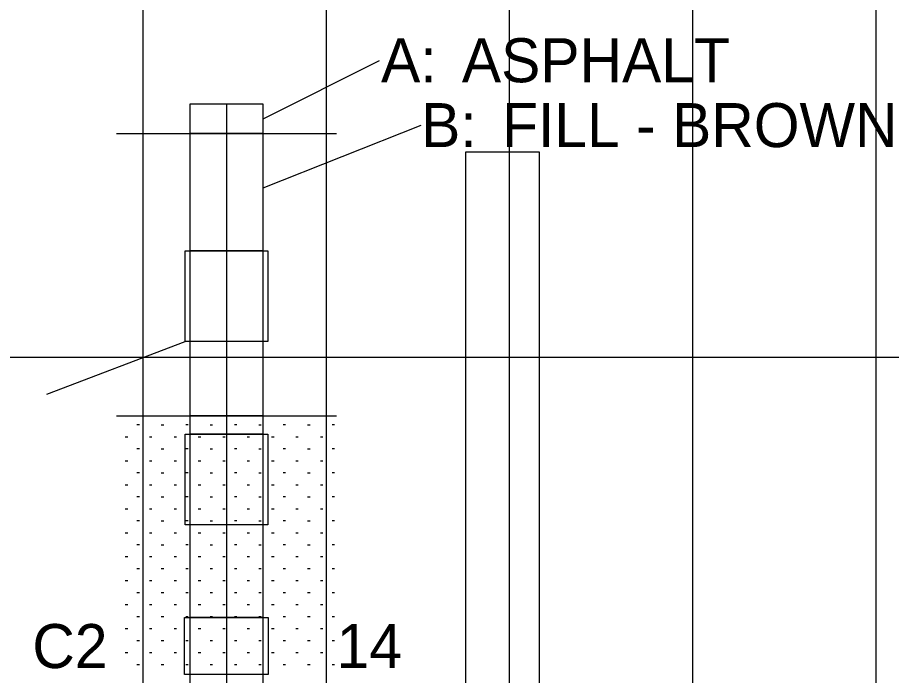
# Model space of a CAD drawing. Extents: x -290 to 297, y 616 to 861.
# Drawn here: x 3.15 to 50.83, y 712.65 to 748.52 of the extents above; entities that cross this region are included whole.
import ezdxf

# ---------------------------------------------------------------- set-up
doc = ezdxf.new("R2010")
doc.units = 0
for name, color, linetype in [('Default', 7, 'Continuous'), ('DisROW Proposed Temp Easements', 7, 'Continuous'), ('Draft_4', 7, 'Continuous'), ('MeshTop', 7, 'Continuous'), ('SewerSanitary', 7, 'Continuous'), ('SewerStormPipe', 7, 'Continuous'), ('TextAlignment', 7, 'Continuous'), ('TextAlignmentSml', 7, 'Continuous'), ('Utility-Water - alignment', 7, 'Continuous'), ('V-SWLK-CONC', 7, 'Continuous')]:
    doc.layers.add(name, color=color, linetype=linetype)

msp = doc.modelspace()

# ---------------------------------------------------------------- linework, layer by layer
at = {"layer": 'Default'}
for p, q in [((14.546, 743.8), (14.546, 682.8)), ((16.546, 742.2), (12.546, 742.2)), ((16.546, 726.8), (12.546, 726.8))]:
    msp.add_line(p, q, dxfattribs=at)
at = {"layer": 'DisROW Proposed Temp Easements'}
for points in [[(12.291, 735.8), (16.801, 735.8), (16.801, 730.863), (12.291, 730.863)], [(12.291, 725.8), (16.801, 725.8), (16.801, 720.863), (12.291, 720.863)], [(12.258, 715.8), (16.834, 715.8), (16.834, 712.704), (12.258, 712.704)]]:
    msp.add_lwpolyline(points, close=True, dxfattribs=at)
at = {"layer": 'Draft_4'}
msp.add_lwpolyline([(16.546, 726.8), (12.546, 726.8), (12.546, 705.8), (16.546, 705.8)], close=True, dxfattribs=at)
at = {"layer": 'MeshTop'}
msp.add_lwpolyline([(16.546, 743.8), (12.546, 743.8), (12.546, 742.2), (16.546, 742.2)], close=True, dxfattribs=at)
at = {"layer": 'SewerSanitary'}
for p, q in [((16.546, 735.8), (12.546, 735.8)), ((16.546, 725.8), (12.546, 725.8))]:
    msp.add_line(p, q, dxfattribs=at)
at = {"layer": 'SewerStormPipe'}
msp.add_line((16.546, 715.8), (12.546, 715.8), dxfattribs=at)
at = {"layer": 'TextAlignment'}
for p, q in [((20, 630), (20, 787.989)), ((40, 630), (40, 787.989)), ((-275.612, 730), (284.208, 730))]:
    msp.add_line(p, q, dxfattribs=at)
at = {"layer": 'TextAlignmentSml'}
for p, q in [((10, 630), (10, 787.989)), ((30, 630), (30, 787.989)), ((50, 630), (50, 787.989))]:
    msp.add_line(p, q, dxfattribs=at)
at = {"layer": 'Utility-Water - alignment'}
msp.add_lwpolyline([(16.546, 742.2), (12.546, 742.2), (12.546, 726.8), (16.546, 726.8)], close=True, dxfattribs=at)
at = {"layer": 'V-SWLK-CONC'}
for p, q in [((16.546, 743), (22.898, 746.185)), ((16.546, 739.24), (25.17, 742.655)), ((8.546, 742.2), (20.546, 742.2)), ((4.756, 727.978), (12.291, 730.863)), ((8.546, 726.8), (20.546, 726.8)), ((9.667, 726.33), (9.799, 726.33)), ((10.996, 726.317), (11.128, 726.317)), ((12.327, 726.33), (12.459, 726.33)), ((13.657, 726.317), (13.789, 726.317)), ((14.988, 726.33), (15.12, 726.33)), ((16.317, 726.317), (16.449, 726.317)), ((17.649, 726.33), (17.781, 726.33)), ((18.978, 726.317), (19.11, 726.317)), ((20.31, 726.33), (20.442, 726.33)), ((9.032, 725.663), (9.164, 725.663)), ((10.352, 725.663), (10.484, 725.663)), ((11.693, 725.663), (11.825, 725.663)), ((13.013, 725.663), (13.145, 725.663)), ((14.354, 725.663), (14.486, 725.663)), ((15.674, 725.663), (15.806, 725.663)), ((17.015, 725.663), (17.147, 725.663)), ((18.335, 725.663), (18.467, 725.663)), ((19.675, 725.663), (19.807, 725.663)), ((9.667, 725.023), (9.799, 725.023)), ((10.996, 725.01), (11.128, 725.01)), ((12.327, 725.023), (12.459, 725.023)), ((13.657, 725.01), (13.789, 725.01)), ((14.988, 725.023), (15.12, 725.023)), ((16.317, 725.01), (16.449, 725.01)), ((17.649, 725.023), (17.781, 725.023)), ((18.978, 725.01), (19.11, 725.01)), ((20.31, 725.023), (20.442, 725.023)), ((9.032, 724.356), (9.164, 724.356)), ((10.352, 724.356), (10.484, 724.356)), ((11.693, 724.356), (11.825, 724.356)), ((13.013, 724.356), (13.145, 724.356)), ((14.354, 724.356), (14.486, 724.356)), ((15.674, 724.356), (15.806, 724.356)), ((17.015, 724.356), (17.147, 724.356)), ((18.335, 724.356), (18.467, 724.356)), ((19.675, 724.356), (19.807, 724.356)), ((9.667, 723.715), (9.799, 723.715)), ((10.996, 723.702), (11.128, 723.702)), ((12.327, 723.715), (12.459, 723.715)), ((13.657, 723.702), (13.789, 723.702)), ((14.988, 723.715), (15.12, 723.715)), ((16.317, 723.702), (16.449, 723.702)), ((17.649, 723.715), (17.781, 723.715)), ((18.978, 723.702), (19.11, 723.702)), ((20.31, 723.715), (20.442, 723.715)), ((9.032, 723.048), (9.164, 723.048)), ((10.352, 723.048), (10.484, 723.048)), ((11.693, 723.048), (11.825, 723.048)), ((13.013, 723.048), (13.145, 723.048)), ((14.354, 723.048), (14.486, 723.048)), ((15.674, 723.048), (15.806, 723.048)), ((17.015, 723.048), (17.147, 723.048)), ((18.335, 723.048), (18.467, 723.048)), ((19.675, 723.048), (19.807, 723.048)), ((9.667, 722.408), (9.799, 722.408)), ((10.996, 722.395), (11.128, 722.395)), ((12.327, 722.408), (12.459, 722.408)), ((13.657, 722.395), (13.789, 722.395)), ((14.988, 722.408), (15.12, 722.408)), ((16.317, 722.395), (16.449, 722.395)), ((17.649, 722.408), (17.781, 722.408)), ((18.978, 722.395), (19.11, 722.395)), ((20.31, 722.408), (20.442, 722.408)), ((9.032, 721.741), (9.164, 721.741)), ((10.352, 721.741), (10.484, 721.741)), ((11.693, 721.741), (11.825, 721.741)), ((13.013, 721.741), (13.145, 721.741)), ((14.354, 721.741), (14.486, 721.741)), ((15.674, 721.741), (15.806, 721.741)), ((17.015, 721.741), (17.147, 721.741)), ((18.335, 721.741), (18.467, 721.741)), ((19.675, 721.741), (19.807, 721.741)), ((9.667, 721.1), (9.799, 721.1)), ((10.996, 721.087), (11.128, 721.087)), ((12.327, 721.1), (12.459, 721.1)), ((13.657, 721.087), (13.789, 721.087)), ((14.988, 721.1), (15.12, 721.1)), ((16.317, 721.087), (16.449, 721.087)), ((17.649, 721.1), (17.781, 721.1)), ((18.978, 721.087), (19.11, 721.087)), ((20.31, 721.1), (20.442, 721.1)), ((9.032, 720.433), (9.164, 720.433)), ((10.352, 720.433), (10.484, 720.433)), ((11.693, 720.433), (11.825, 720.433)), ((13.013, 720.433), (13.145, 720.433)), ((14.354, 720.433), (14.486, 720.433)), ((15.674, 720.433), (15.806, 720.433)), ((17.015, 720.433), (17.147, 720.433)), ((18.335, 720.433), (18.467, 720.433)), ((19.675, 720.433), (19.807, 720.433)), ((9.667, 719.793), (9.799, 719.793)), ((10.996, 719.779), (11.128, 719.779)), ((12.327, 719.793), (12.459, 719.793)), ((13.657, 719.779), (13.789, 719.779)), ((14.988, 719.793), (15.12, 719.793)), ((16.317, 719.779), (16.449, 719.779)), ((17.649, 719.793), (17.781, 719.793)), ((18.978, 719.779), (19.11, 719.779)), ((20.31, 719.793), (20.442, 719.793)), ((9.032, 719.126), (9.164, 719.126)), ((10.352, 719.126), (10.484, 719.126)), ((11.693, 719.126), (11.825, 719.126)), ((13.013, 719.126), (13.145, 719.126)), ((14.354, 719.126), (14.486, 719.126)), ((15.674, 719.126), (15.806, 719.126)), ((17.015, 719.126), (17.147, 719.126)), ((18.335, 719.126), (18.467, 719.126)), ((19.675, 719.126), (19.807, 719.126)), ((9.667, 718.485), (9.799, 718.485)), ((10.996, 718.472), (11.128, 718.472)), ((12.327, 718.485), (12.459, 718.485)), ((13.657, 718.472), (13.789, 718.472)), ((14.988, 718.485), (15.12, 718.485)), ((16.317, 718.472), (16.449, 718.472)), ((17.649, 718.485), (17.781, 718.485)), ((18.978, 718.472), (19.11, 718.472)), ((20.31, 718.485), (20.442, 718.485)), ((9.032, 717.818), (9.164, 717.818)), ((10.352, 717.818), (10.484, 717.818)), ((11.693, 717.818), (11.825, 717.818)), ((13.013, 717.818), (13.145, 717.818)), ((14.354, 717.818), (14.486, 717.818)), ((15.674, 717.818), (15.806, 717.818)), ((17.015, 717.818), (17.147, 717.818)), ((18.335, 717.818), (18.467, 717.818)), ((19.675, 717.818), (19.807, 717.818)), ((9.667, 717.178), (9.799, 717.178)), ((10.996, 717.164), (11.128, 717.164)), ((12.327, 717.178), (12.459, 717.178)), ((13.657, 717.164), (13.789, 717.164)), ((14.988, 717.178), (15.12, 717.178)), ((16.317, 717.164), (16.449, 717.164)), ((17.649, 717.178), (17.781, 717.178)), ((18.978, 717.164), (19.11, 717.164)), ((20.31, 717.178), (20.442, 717.178)), ((9.032, 716.511), (9.164, 716.511)), ((10.352, 716.511), (10.484, 716.511)), ((11.693, 716.511), (11.825, 716.511)), ((13.013, 716.511), (13.145, 716.511)), ((14.354, 716.511), (14.486, 716.511)), ((15.674, 716.511), (15.806, 716.511)), ((17.015, 716.511), (17.147, 716.511)), ((18.335, 716.511), (18.467, 716.511)), ((19.675, 716.511), (19.807, 716.511)), ((9.667, 715.87), (9.799, 715.87)), ((10.996, 715.857), (11.128, 715.857)), ((12.327, 715.87), (12.459, 715.87)), ((13.657, 715.857), (13.789, 715.857)), ((14.988, 715.87), (15.12, 715.87)), ((16.317, 715.857), (16.449, 715.857)), ((17.649, 715.87), (17.781, 715.87)), ((18.978, 715.857), (19.11, 715.857)), ((20.31, 715.87), (20.442, 715.87)), ((9.032, 715.203), (9.164, 715.203)), ((10.352, 715.203), (10.484, 715.203)), ((11.693, 715.203), (11.825, 715.203)), ((13.013, 715.203), (13.145, 715.203)), ((14.354, 715.203), (14.486, 715.203)), ((15.674, 715.203), (15.806, 715.203)), ((17.015, 715.203), (17.147, 715.203)), ((18.335, 715.203), (18.467, 715.203)), ((19.675, 715.203), (19.807, 715.203)), ((9.667, 714.563), (9.799, 714.563)), ((10.996, 714.549), (11.128, 714.549)), ((12.327, 714.563), (12.459, 714.563)), ((13.657, 714.549), (13.789, 714.549)), ((14.988, 714.563), (15.12, 714.563)), ((16.317, 714.549), (16.449, 714.549)), ((17.649, 714.563), (17.781, 714.563)), ((18.978, 714.549), (19.11, 714.549)), ((20.31, 714.563), (20.442, 714.563)), ((9.032, 713.896), (9.164, 713.896)), ((10.352, 713.896), (10.484, 713.896)), ((11.693, 713.896), (11.825, 713.896)), ((13.013, 713.896), (13.145, 713.896)), ((14.354, 713.896), (14.486, 713.896)), ((15.674, 713.896), (15.806, 713.896)), ((17.015, 713.896), (17.147, 713.896)), ((18.335, 713.896), (18.467, 713.896)), ((19.675, 713.896), (19.807, 713.896)), ((9.667, 713.255), (9.799, 713.255)), ((10.996, 713.242), (11.128, 713.242)), ((12.327, 713.255), (12.459, 713.255)), ((13.657, 713.242), (13.789, 713.242)), ((14.988, 713.255), (15.12, 713.255)), ((16.317, 713.242), (16.449, 713.242)), ((17.649, 713.255), (17.781, 713.255)), ((18.978, 713.242), (19.11, 713.242)), ((20.31, 713.255), (20.442, 713.255))]:
    msp.add_line(p, q, dxfattribs=at)
msp.add_lwpolyline([(27.606, 741.2), (31.606, 741.2), (31.606, 680.2), (27.606, 680.2)], close=True, dxfattribs=at)

# ---------------------------------------------------------------- texts
for s, p in [('A: ', (22.985, 744.991)), ('ASPHALT', (27.393, 744.991)), ('B: ', (25.17, 741.455)), ('FILL - BROWN FIRM SANDY CLAY', (29.586, 741.455)), ('C2', (3.961, 713.052)), ('14', (20.555, 713.052))]:
    msp.add_text(s, height=2.4, dxfattribs=at).set_placement(p)

doc.saveas('drawing.dxf')
